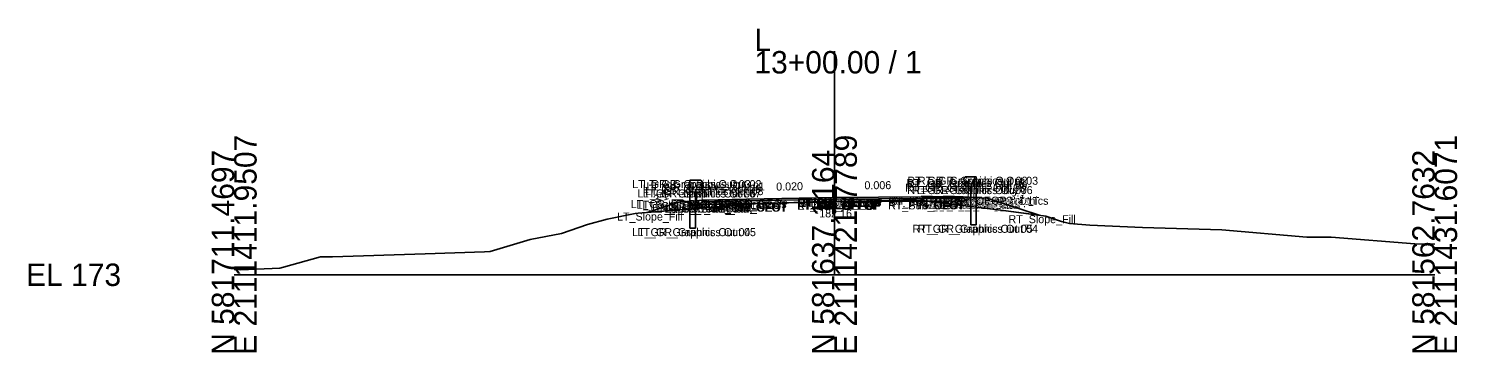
# Model space of a CAD drawing. Extents: x -486 to 1153, y -333 to 9539.
# Drawn here: x -25.7 to 152.8, y 2490.3 to 2530.7 of the extents above; entities that cross this region are included whole.
import ezdxf

# ---------------------------------------------------------------- set-up
doc = ezdxf.new("R2010")
doc.units = 0
for name, color, linetype in [('Default', 7, 'Continuous'), ('Exist Cross Section Cell', 7, 'Continuous'), ('Exist XS Ground Line', 7, 'Continuous'), ('Prop CMT Guardrail Graphics', 7, 'Continuous'), ('Prop CMT Pvmt Course 1', 7, 'Continuous'), ('Prop CMT Pvmt Course 2', 7, 'Continuous'), ('Prop CMT Pvmt Course 3', 7, 'Continuous'), ('Prop CMT Pvmt Surface', 7, 'Continuous'), ('Prop CMT Pvmt Surface Shoulder', 7, 'Continuous'), ('Prop CMT Shld Paved Course 1', 7, 'Continuous'), ('Prop CMT Shld Paved Course 2', 7, 'Continuous'), ('Prop CMT Shld Paved Course 3', 7, 'Continuous'), ('Prop CMT Slope Grass', 7, 'Continuous'), ('Prop CMT Subgrade Earthwork', 7, 'Continuous'), ('Prop XS Earthwork Shape', 7, 'Continuous'), ('Prop XS SE Text', 7, 'Continuous'), ('Prop XS Side Slope Text', 7, 'Continuous'), ('Scratch_Level_0', 7, 'Continuous')]:
    doc.layers.add(name, color=color, linetype=linetype)

msp = doc.modelspace()

# ---------------------------------------------------------------- linework, layer by layer
at = {"layer": 'Exist Cross Section Cell'}
for p, q in [((75, 2500), (75, 2527.93)), ((0, 2500), (75, 2500)), ((75, 2500), (150, 2500))]:
    msp.add_line(p, q, dxfattribs=at)
at = {"layer": 'Exist XS Ground Line'}
for p, q in [((50.49, 2507.68), (64.26, 2508.82)), ((64.26, 2508.82), (65.09, 2508.85)), ((65.09, 2508.85), (73.54, 2509.14)), ((73.54, 2509.14), (74.56, 2509.15)), ((74.56, 2509.15), (75, 2509.16)), ((75, 2509.16), (83.22, 2509.28)), ((83.22, 2509.28), (83.56, 2509.3)), ((83.56, 2509.3), (84.78, 2509.31)), ((84.78, 2509.31), (85.22, 2509.31)), ((85.22, 2509.31), (86.05, 2509.26)), ((86.05, 2509.26), (96.14, 2508.01)), ((44.13, 2506.26), (46.62, 2506.96)), ((46.62, 2506.96), (50.12, 2507.63)), ((50.12, 2507.63), (50.49, 2507.68)), ((96.14, 2508.01), (101.42, 2507.33)), ((101.42, 2507.33), (103.36, 2506.64)), ((103.36, 2506.64), (104.38, 2506.38)), ((36.98, 2504.4), (40.88, 2505.15)), ((40.88, 2505.15), (44.13, 2506.26)), ((104.38, 2506.38), (106.89, 2506.21)), ((106.89, 2506.21), (113.47, 2505.88)), ((113.47, 2505.88), (123.39, 2505.62)), ((123.39, 2505.62), (134.04, 2504.7)), ((32, 2502.89), (36.98, 2504.4)), ((134.04, 2504.7), (137.08, 2504.69)), ((137.08, 2504.69), (147.52, 2503.88)), ((147.52, 2503.88), (150, 2503.83)), ((6.14, 2500.94), (10.78, 2502.22)), ((10.78, 2502.22), (12.3, 2502.25)), ((12.3, 2502.25), (23.86, 2502.62)), ((23.86, 2502.62), (31.26, 2502.86)), ((31.26, 2502.86), (32, 2502.89)), ((0, 2500.64), (0.82, 2500.62)), ((0.82, 2500.62), (5.69, 2500.81)), ((5.69, 2500.81), (6.14, 2500.94))]:
    msp.add_line(p, q, dxfattribs=at)
at = {"layer": 'Prop CMT Guardrail Graphics'}
for points in [[(92.7, 2512.24), (91.37, 2512.24), (91.1, 2511.95)], [(92.7, 2506.24), (92.7, 2512.24)], [(56.95, 2505.82), (56.95, 2511.82)], [(56.95, 2511.82), (58.29, 2511.82), (58.56, 2511.52)], [(58.56, 2510.94), (58.29, 2510.65), (57.62, 2510.65)], [(57.62, 2510.65), (57.62, 2505.82)], [(58.56, 2511.52), (58.29, 2511.23)], [(58.29, 2511.23), (58.56, 2510.94)], [(91.1, 2511.95), (91.37, 2511.66)], [(91.37, 2511.66), (91.1, 2511.37)], [(91.1, 2511.37), (91.37, 2511.07), (92.04, 2511.07)], [(92.04, 2511.07), (92.04, 2506.24)], [(57.62, 2505.82), (56.95, 2505.82)], [(92.04, 2506.24), (92.7, 2506.24)]]:
    msp.add_lwpolyline(points, dxfattribs=at)
at = {"layer": 'Prop CMT Pvmt Course 1'}
for points in [[(75, 2509.65), (64, 2509.43)], [(64, 2509.22), (75, 2509.44)], [(64, 2509.43), (64, 2509.22)], [(75, 2509.65), (86, 2509.72)], [(75, 2509.44), (75, 2509.65)], [(75, 2509.44), (75, 2509.65)], [(86, 2509.51), (75, 2509.44)], [(86, 2509.72), (86, 2509.51)]]:
    msp.add_lwpolyline(points, dxfattribs=at)
msp.add_lwpolyline([(75, 2509.44), (75, 2509.53), (75, 2509.53), (75, 2509.44)], close=True, dxfattribs=at)
msp.add_lwpolyline([(75, 2509.44), (75, 2509.53), (75, 2509.53), (75, 2509.44)], close=True, dxfattribs=at)
at = {"layer": 'Prop CMT Pvmt Course 2'}
for points in [[(75, 2509.44), (64, 2509.22)], [(64, 2509.22), (64, 2508.89)], [(64, 2508.89), (75, 2509.11)], [(75, 2509.44), (86, 2509.51)], [(75, 2509.11), (75, 2509.44)], [(75, 2509.11), (75, 2509.44)], [(86, 2509.17), (75, 2509.11)], [(86, 2509.51), (86, 2509.17)]]:
    msp.add_lwpolyline(points, dxfattribs=at)
at = {"layer": 'Prop CMT Pvmt Course 3'}
for points in [[(75, 2509.11), (64, 2508.89)], [(64, 2508.89), (64, 2508.89)], [(75, 2509.11), (86, 2509.17)], [(75, 2509.11), (75, 2509.11)], [(75, 2509.11), (75, 2509.11)], [(86, 2509.17), (86, 2509.17)]]:
    msp.add_lwpolyline(points, dxfattribs=at)
at = {"layer": 'Prop CMT Pvmt Surface'}
for points in [[(75, 2509.65), (64, 2509.43)], [(75, 2509.65), (86, 2509.72)]]:
    msp.add_lwpolyline(points, dxfattribs=at)
at = {"layer": 'Prop CMT Pvmt Surface Shoulder'}
for points in [[(64, 2509.43), (58.66, 2509.32)], [(86, 2509.72), (91, 2509.75)]]:
    msp.add_lwpolyline(points, dxfattribs=at)
at = {"layer": 'Prop CMT Shld Paved Course 1'}
for points in [[(64, 2509.43), (58.66, 2509.32), (58.44, 2509.11)], [(58.44, 2509.11), (64, 2509.22)], [(64, 2509.22), (64, 2509.43)], [(86, 2509.72), (91, 2509.75), (91.21, 2509.54)], [(86, 2509.51), (86, 2509.72)], [(91.21, 2509.54), (86, 2509.51)]]:
    msp.add_lwpolyline(points, dxfattribs=at)
at = {"layer": 'Prop CMT Shld Paved Course 2'}
for points in [[(64, 2509.22), (58.44, 2509.11), (58.1, 2508.77)], [(58.1, 2508.77), (64, 2508.89)], [(64, 2508.89), (64, 2509.22)], [(86, 2509.51), (91.21, 2509.54), (91.54, 2509.21)], [(86, 2509.17), (86, 2509.51)], [(91.54, 2509.21), (86, 2509.17)]]:
    msp.add_lwpolyline(points, dxfattribs=at)
at = {"layer": 'Prop CMT Shld Paved Course 3'}
for points in [[(64, 2508.89), (58.1, 2508.77)], [(58.1, 2508.77), (58.1, 2508.77), (58.1, 2508.77)], [(64, 2508.89), (64, 2508.89)], [(86, 2509.17), (91.54, 2509.21)], [(86, 2509.17), (86, 2509.17)], [(91.54, 2509.21), (91.54, 2509.21), (91.54, 2509.21)]]:
    msp.add_lwpolyline(points, dxfattribs=at)
at = {"layer": 'Prop CMT Slope Grass'}
for points in [[(58.66, 2509.32), (55.56, 2509.08), (51.6, 2507.77)], [(55.56, 2509.08), (51.6, 2507.77)], [(58.56, 2509.32), (55.56, 2509.08)], [(58.66, 2509.32), (58.56, 2509.32)], [(91, 2509.75), (91.1, 2509.74)], [(91.1, 2509.74), (94.1, 2509.58)], [(94.1, 2509.58), (100.57, 2507.44)]]:
    msp.add_lwpolyline(points, dxfattribs=at)
at = {"layer": 'Prop CMT Subgrade Earthwork'}
for points in [[(58.1, 2508.77), (57.63, 2509.24)], [(64, 2508.89), (58.1, 2508.77)], [(75, 2509.11), (64, 2508.89)], [(75, 2509.11), (86, 2509.17)], [(86, 2509.17), (91.54, 2509.21)], [(91.54, 2509.21), (92.02, 2509.69)]]:
    msp.add_lwpolyline(points, dxfattribs=at)
at = {"layer": 'Prop XS Earthwork Shape'}
for points in [[(55.56, 2509.08), (51.6, 2507.77), (64.26, 2508.82), (65.09, 2508.85), (69.26, 2508.99), (64, 2508.89), (58.1, 2508.77), (57.63, 2509.24)], [(69.26, 2508.99), (73.54, 2509.14), (74.56, 2509.15), (75, 2509.16), (83.22, 2509.28), (83.56, 2509.3), (84.78, 2509.31), (85.22, 2509.31), (86.05, 2509.26), (86.67, 2509.18), (86, 2509.17), (75, 2509.11)], [(92.02, 2509.69), (94.1, 2509.58), (100.57, 2507.44), (96.14, 2508.01), (86.67, 2509.18), (91.54, 2509.21)]]:
    msp.add_lwpolyline(points, close=True, dxfattribs=at)

# ---------------------------------------------------------------- texts
at = {"layer": 'Default'}
for s, height, p in [('182.16', 1, (73.1, 2507.16)), ('-', 0.0001, (0, 2500))]:
    msp.add_text(s, height=height, dxfattribs=at).set_placement(p)
at = {"layer": 'Exist Cross Section Cell'}
for s, p in [('L', (65, 2527.93)), ('13+00.00 / 1', (65, 2525.13)), ('EL 173', (-26, 2498.6))]:
    msp.add_text(s, height=2.8, dxfattribs=at).set_placement(p)
for s, p in [('E 2111411.9507', (2.8, 2490)), ('E 2111421.7789', (77.8, 2490)), ('E 2111431.6071', (152.8, 2490)), ('N 581711.4697', (0, 2490)), ('N 581637.1164', (75, 2490)), ('N 581562.7632', (150, 2490))]:
    msp.add_text(s, height=2.8, rotation=90, dxfattribs=at).set_placement(p)
at = {"layer": 'Prop XS SE Text'}
for s, rotation, p in [('0.020', 1.1458, (67.73, 2510.5)), ('0.006', 0.3438, (78.75, 2510.67))]:
    msp.add_text(s, height=1, rotation=rotation, dxfattribs=at).set_placement(p)
at = {"layer": 'Prop XS Side Slope Text'}
for rotation, p in [(18.2629, (52.59, 2508.89)), (341.7371, (96.82, 2509.47))]:
    msp.add_text('3:1', height=1, rotation=rotation, dxfattribs=at).set_placement(p)
at = {"layer": 'Scratch_Level_0'}
for s, p in [('RT_GR_Graphics Out 01', (83.99, 2510.95)), ('RT_GR_Graphics Out 02', (84.11, 2511.24)), ('RT_GR_Graphics Out 03', (85.43, 2511.24)), ('LT_GR_Graphics Out 03', (49.74, 2510.82)), ('LT_GR_Graphics Out 06', (50.39, 2509.65)), ('LT_GR_Graphics Out 07', (51.04, 2509.65)), ('LT_GR_Graphics Out 09', (51.06, 2510.23)), ('LT_GR_Graphics Out 02', (51.09, 2510.82)), ('LT_GR_Graphics Out 08', (51.33, 2509.94)), ('LT_GR_Graphics Out 01', (51.5, 2510.52)), ('RT_GR_Graphics Out 08', (83.81, 2510.37)), ('RT_GR_Graphics Out 07', (84.07, 2510.07)), ('RT_GR_Graphics Out 09', (84.09, 2510.66)), ('RT_GR_Graphics Out 06', (84.75, 2510.07)), ('LT_GS_OS_GR_Face_Graphics', (49.55, 2508.32)), ('LT_Sub_Trench_Out_DLT', (50.28, 2508.24)), ('LT_GS_OS_CTL', (51.02, 2508.08)), ('LT_Sub_Trench_Out', (52.21, 2507.77)), ('LT_PS3_Shelf_Out', (52.76, 2507.77)), ('LT_PS3_OEOP', (53.89, 2507.77)), ('LT_PS2_OEOP', (54.23, 2508.11)), ('LT_PS1_OEOP', (54.56, 2508.32)), ('LT_PV2_OEOT', (59.75, 2508.22)), ('LT_PV3_OEOT', (59.75, 2507.89)), ('LT_Sub_OEOT', (59.77, 2507.89)), ('LT_PV1_OEOT', (59.87, 2508.43)), ('RT_PV2_OEEOP', (70.33, 2508.44)), ('RT_PV3_OEEOP', (70.33, 2508.11)), ('RT_Sub_OEEOP', (70.36, 2508.11)), ('LT_PV2_OEEOP', (70.39, 2508.44)), ('LT_PV3_OEEOP', (70.39, 2508.11)), ('LT_Sub_OEEOP', (70.42, 2508.11)), ('RT_PV1_OEEOP', (70.45, 2508.53)), ('LT_PV1_OEEOP', (70.51, 2508.53)), ('RT_PV2_IEEOP', (70.71, 2508.44)), ('LT_PV2_IEEOP', (70.77, 2508.44)), ('RT_PV1_IEEOP', (70.83, 2508.53)), ('LT_PV1_IEEOP', (70.89, 2508.53)), ('PV2_PGL', (72.35, 2508.44)), ('PV1_PGL', (72.47, 2508.65)), ('RT_PV2_OEOT', (81.69, 2508.51)), ('RT_PV3_OEOT', (81.69, 2508.17)), ('RT_Sub_OEOT', (81.71, 2508.17)), ('RT_PV1_OEOT', (81.81, 2508.72)), ('RT_GS_OS_GR_Face_Graphics', (82.04, 2508.74)), ('RT_Sub_Trench_Out_DLT', (84.61, 2508.69)), ('RT_Sub_Trench_Out', (85.59, 2508.21)), ('RT_PS3_Shelf_Out', (86.14, 2508.21)), ('RT_PS1_OEOP', (86.85, 2508.75)), ('RT_PS2_OEOP', (86.93, 2508.54)), ('RT_PS3_OEOP', (87.27, 2508.21)), ('RT_GS_OS_CTL', (89.5, 2508.58)), ('LT_Slope_Fill', (47.84, 2506.77)), ('RT_Slope_Fill', (96.75, 2506.44)), ('LT_GR_Graphics Out 04', (49.72, 2504.82)), ('LT_GR_Graphics Out 05', (50.4, 2504.82)), ('RT_GR_Graphics Out 05', (84.76, 2505.24)), ('RT_GR_Graphics Out 04', (85.41, 2505.24))]:
    msp.add_text(s, height=1, dxfattribs=at).set_placement(p)

doc.saveas('drawing.dxf')
